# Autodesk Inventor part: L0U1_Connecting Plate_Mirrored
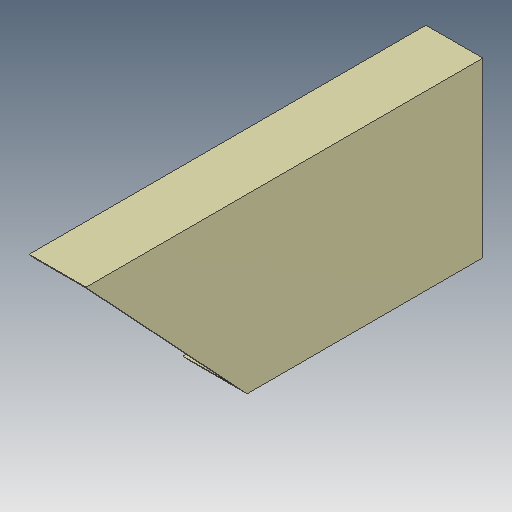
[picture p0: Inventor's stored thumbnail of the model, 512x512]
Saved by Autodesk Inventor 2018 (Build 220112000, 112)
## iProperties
Created: 2018-02
Part Number: L0U1_Connecting Plate_Mirrored
Material: Steel, Mild
Document SubType Name: Modeling
Designer: STK
Density: 7.85 g/cm^3
Appearance: Semi-Polished
Author: STK
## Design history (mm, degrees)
derived "L0U1_Connecting Plate.ipt"
feature "Solid1::L0U1_Connecting Plate.ipt" dims "d0" = 10
tag "TaggingFeature1"
body "Solid1"
